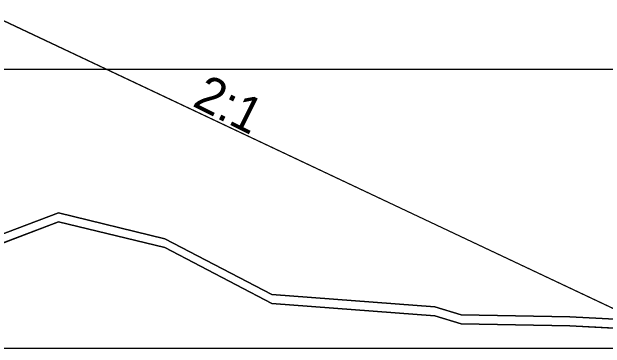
# Model space of a CAD drawing. Extents: x -120 to 2876, y -25 to 8560.
# Drawn here: x 1478.54 to 1495.04, y 1000 to 1009.36 of the extents above; entities that cross this region are included whole.
import ezdxf

# ---------------------------------------------------------------- set-up
doc = ezdxf.new("R2010")
doc.units = 0
for name, color, linetype in [('DESIGN - EARTHWORK - Shapes', 7, 'Continuous'), ('DESIGN - SCRATCH - User 2', 7, 'Continuous'), ('DESIGN - SHEET - Light Grid', 7, 'Continuous'), ('DESIGN - TYPICAL - Finished Grade and Subgrade', 7, 'Continuous'), ('DESIGN - TYPICAL - Finished Grade Slopes Text', 7, 'Continuous'), ('SURVEY - GROUND - Bottom of Topsoil Layer', 7, 'Continuous'), ('SURVEY - GROUND - Top of Ground', 7, 'Continuous')]:
    doc.layers.add(name, color=color, linetype=linetype)

msp = doc.modelspace()

# ---------------------------------------------------------------- linework, layer by layer
at = {"layer": 'DESIGN - EARTHWORK - Shapes'}
msp.add_lwpolyline([(1477.795, 1009.358), (1495.858, 1000.823), (1495.858, 1000.778), (1494.06, 1000.873), (1491.039, 1000.925), (1490.306, 1001.153), (1485.772, 1001.495), (1482.795, 1003.046), (1479.837, 1003.761), (1474.698, 1001.819)], dxfattribs=at)
msp.add_lwpolyline([(1467.868, 1003.481), (1468.823, 1003.135), (1474.159, 1001.634), (1474.698, 1001.819), (1479.837, 1003.761), (1482.795, 1003.046), (1485.772, 1001.495), (1490.306, 1001.153), (1491.039, 1000.925), (1494.06, 1000.873), (1495.858, 1000.778), (1495.858, 1000.528), (1494.06, 1000.623), (1491.039, 1000.675), (1490.306, 1000.903), (1485.772, 1001.245), (1482.795, 1002.796), (1479.837, 1003.511), (1474.698, 1001.569), (1474.159, 1001.384), (1468.823, 1002.885), (1467.868, 1003.231), (1462.615, 1004.537), (1462.615, 1004.787)], close=True, dxfattribs=at)
at = {"layer": 'DESIGN - SCRATCH - User 2'}
msp.add_line((1517.42, 1007.75), (1403.358, 1007.75), dxfattribs=at)
at = {"layer": 'DESIGN - SHEET - Light Grid'}
msp.add_line((1450, 1000), (1600, 1000), dxfattribs=at)
at = {"layer": 'DESIGN - TYPICAL - Finished Grade and Subgrade'}
msp.add_line((1477.795, 1009.358), (1495.858, 1000.823), dxfattribs=at)
at = {"layer": 'SURVEY - GROUND - Bottom of Topsoil Layer'}
for p, q in [((1474.698, 1001.569), (1479.837, 1003.511)), ((1479.837, 1003.511), (1482.795, 1002.796)), ((1482.795, 1002.796), (1485.772, 1001.245)), ((1485.772, 1001.245), (1490.306, 1000.903)), ((1490.306, 1000.903), (1491.039, 1000.675)), ((1491.039, 1000.675), (1494.06, 1000.623)), ((1494.06, 1000.623), (1496.256, 1000.507))]:
    msp.add_line(p, q, dxfattribs=at)
at = {"layer": 'SURVEY - GROUND - Top of Ground'}
msp.add_lwpolyline([(1474.698, 1001.819), (1479.837, 1003.761), (1482.795, 1003.046), (1485.772, 1001.495), (1490.306, 1001.153), (1491.039, 1000.925), (1494.06, 1000.873), (1496.256, 1000.757), (1499.403, 1001.307), (1503.737, 1002.603), (1518.07, 1003.63)], dxfattribs=at)

# ---------------------------------------------------------------- texts
at = {"layer": 'DESIGN - TYPICAL - Finished Grade Slopes Text'}
msp.add_text('2:1', height=1, rotation=333.4349, dxfattribs=at).set_placement((1483.53, 1006.754))

doc.saveas('drawing.dxf')
